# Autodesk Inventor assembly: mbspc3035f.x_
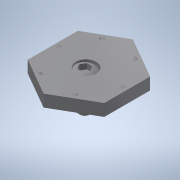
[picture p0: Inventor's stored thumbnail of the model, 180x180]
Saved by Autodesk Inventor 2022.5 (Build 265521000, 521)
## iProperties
Part Number: mbspc3035f.x_
Material: 一般
Document SubType Name: Assembly
Designer: ImaoCorp
Sending System: SOLIDWORKS 2017-2017317
MC: AMD64
MC_MODEL: Intel64 Family 6 Model 60 Stepping 3, GenuineIntel
OS: Windows_NT
FRU: Parasolid Version 29.0, build 201,  4-17-2017
FORMAT: text
GUISE: transmit
KEY: mbspc3035f
FILE: mbspc3035f.x_t
DATE: Fri Jul 26 11:38:40 2019
Author: ImaoCorp
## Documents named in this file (3)
- X:\14_SW2022-Inv2022\00_全2023-1023新製品(TCC)まで\m\mbspc3035f\MBSPC3035F.iam
- X:\14_SW2022-Inv2022\00_全2023-1023新製品(TCC)まで\m\mbspc3035f\mbspc3035f_01.ipt
- X:\14_SW2022-Inv2022\00_全2023-1023新製品(TCC)まで\m\mbspc3035f\mbspc3035f_02.ipt
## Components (2 placed, 2 different names)
1. mbspc3035f_01
2. mbspc3035f_02
